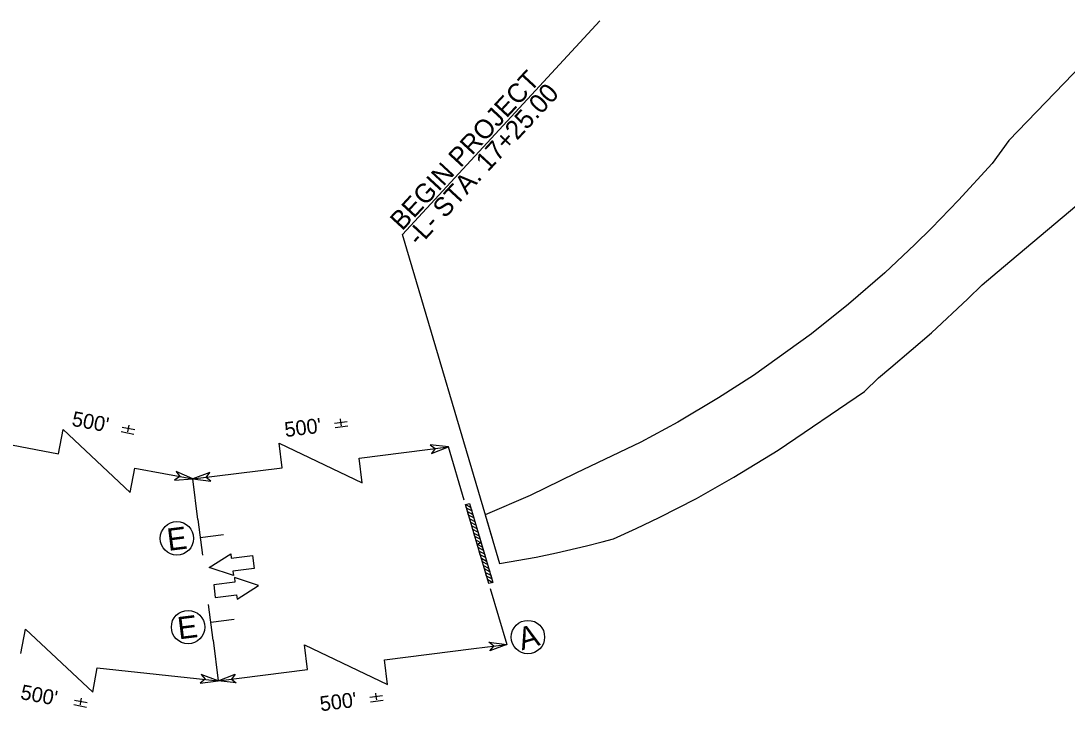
# Model space of a CAD drawing. Extents: x 1767460 to 1770129, y 996106 to 1001438.
# Drawn here: x 1768388.3 to 1768857.4, y 999862 to 1000171.5 of the extents above; entities that cross this region are included whole.
import ezdxf

# ---------------------------------------------------------------- set-up
doc = ezdxf.new("R2010")
doc.units = 0
for name, color, linetype in [('_CIVIL_CONSTRUCTION', 7, 'Continuous'), ('E_NCDOT_Terrain_Model_Contour_Major', 7, 'Continuous'), ('E_NCDOT_Terrain_Model_Spot_Elevation', 7, 'Continuous'), ('E_NCDOT_Terrain_Model_Triangle_Vertices', 7, 'Continuous'), ('E_NCDOT_Terrain_Model_Triangles', 7, 'Continuous'), ('P_RDY_TL_Grass_Shoulder_Normal', 7, 'Continuous')]:
    doc.layers.add(name, color=color, linetype=linetype)

msp = doc.modelspace()

# ---------------------------------------------------------------- linework, layer by layer
at = {"layer": '_CIVIL_CONSTRUCTION'}
for centre in [(1768458.25, 999939.44), (1768463.25, 999899.64), (1768615.65, 999895.18)]:
    msp.add_circle(centre, 7.5, dxfattribs=at)
at = {"layer": 'E_NCDOT_Terrain_Model_Contour_Major'}
msp.add_line((1768602.97, 999928.22), (1768602.97, 999928.22), dxfattribs=at)
for points in [[(1768880.7, 1000169.1), (1768831.33, 1000117.91), (1768823.79, 1000107.54), (1768808.68, 1000091.19), (1768796.64, 1000078.6), (1768789.19, 1000071.21), (1768775.73, 1000058.59), (1768759.43, 1000044.46), (1768742.78, 1000031.18), (1768716.76, 1000012.53), (1768701.13, 1000002.44), (1768682.83, 999991.6), (1768666.22, 999982.61), (1768637.11, 999968.61), (1768616.67, 999958.6)], [(1768602.97, 999928.22), (1768619.33, 999931.05), (1768628.53, 999932.93), (1768641.84, 999936.02), (1768648.89, 999937.84), (1768653.96, 999939.23), (1768664.21, 999943.83), (1768674.48, 999948.73), (1768691.24, 999957.39), (1768707.99, 999966.86), (1768727.78, 999979.07), (1768766.51, 1000005.29), (1768772.79, 1000011.48), (1768778.43, 1000016.05), (1768796.61, 1000031.65), (1768812.92, 1000046.87), (1768819.26, 1000053.12), (1768828.95, 1000061.29), (1768861.74, 1000088.93)], [(1768616.67, 999958.6), (1768596.52, 999950.03), (1768602.97, 999928.22)]]:
    msp.add_lwpolyline(points, dxfattribs=at)
at = {"layer": 'E_NCDOT_Terrain_Model_Spot_Elevation'}
for p, q in [((1768587.64, 999954.63), (1768589.39, 999955.15)), ((1768588.11, 999953.04), (1768587.64, 999954.63)), ((1768587.64, 999954.63), (1768589.94, 999953.38)), ((1768592.89, 999936.91), (1768587.64, 999954.63)), ((1768590.42, 999951.79), (1768588.11, 999953.04)), ((1768589.39, 999955.15), (1768594.63, 999937.42)), ((1768589.94, 999953.38), (1768590.42, 999951.79)), ((1768589.06, 999949.85), (1768588.59, 999951.44)), ((1768588.59, 999951.44), (1768590.89, 999950.19)), ((1768591.36, 999948.6), (1768589.06, 999949.85)), ((1768590.01, 999946.63), (1768589.54, 999948.22)), ((1768589.54, 999948.22), (1768591.83, 999947)), ((1768590.89, 999950.19), (1768591.36, 999948.6)), ((1768592.3, 999945.41), (1768590.01, 999946.63)), ((1768590.95, 999943.44), (1768590.48, 999945.03)), ((1768590.48, 999945.03), (1768592.77, 999943.81)), ((1768593.25, 999942.22), (1768590.95, 999943.44)), ((1768591.83, 999947), (1768592.3, 999945.41)), ((1768592.77, 999943.81), (1768593.25, 999942.22)), ((1768591.9, 999940.25), (1768591.43, 999941.84)), ((1768591.43, 999941.84), (1768593.72, 999940.62)), ((1768594.19, 999939.03), (1768591.9, 999940.25)), ((1768592.89, 999936.91), (1768592.37, 999938.65)), ((1768592.37, 999938.65), (1768594.66, 999937.43)), ((1768593.72, 999940.62), (1768594.19, 999939.03)), ((1768594.66, 999937.43), (1768592.89, 999936.91)), ((1768594.63, 999937.42), (1768592.89, 999936.91)), ((1768592.89, 999936.91), (1768594.63, 999937.42)), ((1768593.36, 999935.31), (1768592.89, 999936.91)), ((1768592.89, 999936.91), (1768595.19, 999935.66)), ((1768598.13, 999919.18), (1768592.89, 999936.91)), ((1768595.66, 999934.06), (1768593.36, 999935.31)), ((1768594.3, 999932.12), (1768593.83, 999933.72)), ((1768593.83, 999933.72), (1768596.13, 999932.47)), ((1768594.63, 999937.42), (1768599.87, 999919.7)), ((1768595.19, 999935.66), (1768595.66, 999934.06)), ((1768596.6, 999930.87), (1768594.3, 999932.12)), ((1768595.25, 999928.9), (1768594.78, 999930.5)), ((1768594.78, 999930.5), (1768597.07, 999929.28)), ((1768597.54, 999927.68), (1768595.25, 999928.9)), ((1768596.13, 999932.47), (1768596.6, 999930.87)), ((1768597.07, 999929.28), (1768597.54, 999927.68)), ((1768596.2, 999925.71), (1768595.72, 999927.31)), ((1768595.72, 999927.31), (1768598.02, 999926.09)), ((1768598.49, 999924.49), (1768596.2, 999925.71)), ((1768597.14, 999922.52), (1768596.67, 999924.12)), ((1768596.67, 999924.12), (1768598.96, 999922.9)), ((1768598.02, 999926.09), (1768598.49, 999924.49)), ((1768599.43, 999921.3), (1768597.14, 999922.52)), ((1768598.13, 999919.18), (1768597.61, 999920.93)), ((1768597.61, 999920.93), (1768599.9, 999919.71)), ((1768599.9, 999919.71), (1768598.13, 999919.18)), ((1768599.87, 999919.7), (1768598.13, 999919.18)), ((1768598.96, 999922.9), (1768599.43, 999921.3))]:
    msp.add_line(p, q, dxfattribs=at)
at = {"layer": 'E_NCDOT_Terrain_Model_Triangle_Vertices'}
for p, q in [((1768467.67, 999947.93), (1768469.69, 999931.86)), ((1768468.69, 999939.83), (1768479.11, 999941.14)), ((1768474.49, 999893.75), (1768472.47, 999909.82)), ((1768473.47, 999901.85), (1768483.88, 999903.16))]:
    msp.add_line(p, q, dxfattribs=at)
at = {"layer": 'E_NCDOT_Terrain_Model_Triangles'}
for p, q in [((1768559.36, 1000075.69), (1768647.93, 1000171.51)), ((1768599.86, 999938.75), (1768559.36, 1000075.69)), ((1768436.49, 999988.74), (1768436.77, 999990.24)), ((1768528.94, 999991.14), (1768534.66, 999991.86)), ((1768529.19, 999989.14), (1768534.91, 999989.86)), ((1768531.8, 999991.5), (1768531.61, 999993.02)), ((1768531.99, 999989.98), (1768531.8, 999991.5)), ((1768365.49, 999984.83), (1768405.13, 999977.38)), ((1768433.29, 999987.3), (1768438.95, 999986.23)), ((1768433.66, 999989.27), (1768439.32, 999988.21)), ((1768436.21, 999987.24), (1768436.49, 999988.74)), ((1768539.97, 999975.44), (1768580, 999980.48)), ((1768580, 999980.48), (1768571.88, 999981.46)), ((1768571.88, 999981.46), (1768574.09, 999979.74)), ((1768572.37, 999977.52), (1768580, 999980.48)), ((1768587.09, 999956.5), (1768580, 999980.48)), ((1768574.09, 999979.74), (1768572.37, 999977.52)), ((1768439.36, 999970.95), (1768465.39, 999966.07)), ((1768465.39, 999966.07), (1768505.42, 999971.1)), ((1768459.54, 999967.16), (1768457.23, 999965.58)), ((1768457.23, 999965.58), (1768465.39, 999966.07)), ((1768465.39, 999966.07), (1768457.96, 999969.48)), ((1768457.96, 999969.48), (1768459.54, 999967.16)), ((1768473.02, 999969.03), (1768465.39, 999966.07)), ((1768465.39, 999966.07), (1768473.52, 999965.09)), ((1768467.67, 999947.93), (1768465.39, 999966.07)), ((1768471.3, 999966.81), (1768473.02, 999969.03)), ((1768473.52, 999965.09), (1768471.3, 999966.81)), ((1768598.76, 999917.03), (1768606.2, 999891.89)), ((1768474.49, 999893.75), (1768476.77, 999875.62)), ((1768591.37, 999890.03), (1768606.2, 999891.89)), ((1768598.07, 999892.87), (1768606.2, 999891.89)), ((1768600.29, 999891.15), (1768598.07, 999892.87)), ((1768606.2, 999891.89), (1768598.57, 999888.93)), ((1768598.57, 999888.93), (1768600.29, 999891.15)), ((1768551.35, 999885), (1768591.37, 999890.03)), ((1768422.54, 999881.36), (1768476.77, 999875.62)), ((1768476.77, 999875.62), (1768469.08, 999878.43)), ((1768469.08, 999878.43), (1768470.85, 999876.24)), ((1768476.77, 999875.62), (1768516.79, 999880.65)), ((1768476.77, 999875.62), (1768484.39, 999878.58)), ((1768484.39, 999878.58), (1768482.67, 999876.36)), ((1768470.85, 999876.24), (1768468.66, 999874.48)), ((1768468.66, 999874.48), (1768476.77, 999875.62)), ((1768484.89, 999874.64), (1768476.77, 999875.62)), ((1768482.67, 999876.36), (1768484.89, 999874.64)), ((1768415.24, 999866.31), (1768415.52, 999867.82)), ((1768544.78, 999868.18), (1768550.49, 999868.9)), ((1768547.63, 999868.54), (1768547.44, 999870.06)), ((1768547.83, 999867.03), (1768547.63, 999868.54)), ((1768412.03, 999864.87), (1768417.7, 999863.8)), ((1768412.4, 999866.84), (1768418.07, 999865.78)), ((1768414.95, 999864.81), (1768415.24, 999866.31)), ((1768545.03, 999866.19), (1768550.74, 999866.91))]:
    msp.add_line(p, q, dxfattribs=at)
for points in [[(1768405.13, 999977.38), (1768407.19, 999988.34), (1768437.31, 999960), (1768439.36, 999970.95)], [(1768505.42, 999971.1), (1768504.03, 999982.16), (1768541.36, 999964.39), (1768539.97, 999975.44)], [(1768388.31, 999887.79), (1768390.36, 999898.74), (1768420.48, 999870.41), (1768422.54, 999881.36)], [(1768516.79, 999880.65), (1768515.4, 999891.71), (1768552.74, 999873.94), (1768551.35, 999885)]]:
    msp.add_lwpolyline(points, dxfattribs=at)
at = {"layer": 'P_RDY_TL_Grass_Shoulder_Normal'}
for p, q in [((1768472.71, 999926.37), (1768482.36, 999932.49)), ((1768482.36, 999932.49), (1768482.6, 999930.53)), ((1768482.6, 999930.53), (1768492.13, 999931.73)), ((1768492.13, 999931.73), (1768492.85, 999925.98)), ((1768483.57, 999922.83), (1768472.71, 999926.37)), ((1768492.85, 999925.98), (1768483.33, 999924.78)), ((1768483.33, 999924.78), (1768483.57, 999922.83)), ((1768484.27, 999919.87), (1768474.75, 999918.67)), ((1768494.89, 999918.28), (1768484.03, 999921.82)), ((1768484.03, 999921.82), (1768484.27, 999919.87)), ((1768474.75, 999918.67), (1768475.47, 999912.92)), ((1768485.24, 999912.16), (1768494.89, 999918.28)), ((1768475.47, 999912.92), (1768484.99, 999914.12)), ((1768484.99, 999914.12), (1768485.24, 999912.16))]:
    msp.add_line(p, q, dxfattribs=at)

# ---------------------------------------------------------------- texts
at = {"layer": '_CIVIL_CONSTRUCTION'}
for s, rotation, p in [('E', 7.1677, (1768454.46, 999933.8)), ('E', 7.1677, (1768459.16, 999894.11)), ('A', 16.4744, (1768612.96, 999889.17))]:
    msp.add_text(s, height=10, rotation=rotation, dxfattribs=at).set_placement(p)
at = {"layer": 'E_NCDOT_Terrain_Model_Triangles'}
for s, height, rotation, p in [('BEGIN PROJECT', 8.5, 47.2512, (1768559.28, 1000077.06)), ('-L- STA. 17+25.00', 8.5, 47.2512, (1768566.81, 1000070.11)), ("500'", 6.667, 349.3623, (1768410.77, 999990)), ("500'", 6.667, 7.1677, (1768506.93, 999984.84)), ("500'", 6.667, 349.3623, (1768387.75, 999867.43)), ("500'", 6.667, 7.1677, (1768522.76, 999861.88))]:
    msp.add_text(s, height=height, rotation=rotation, dxfattribs=at).set_placement(p)

doc.saveas('drawing.dxf')
